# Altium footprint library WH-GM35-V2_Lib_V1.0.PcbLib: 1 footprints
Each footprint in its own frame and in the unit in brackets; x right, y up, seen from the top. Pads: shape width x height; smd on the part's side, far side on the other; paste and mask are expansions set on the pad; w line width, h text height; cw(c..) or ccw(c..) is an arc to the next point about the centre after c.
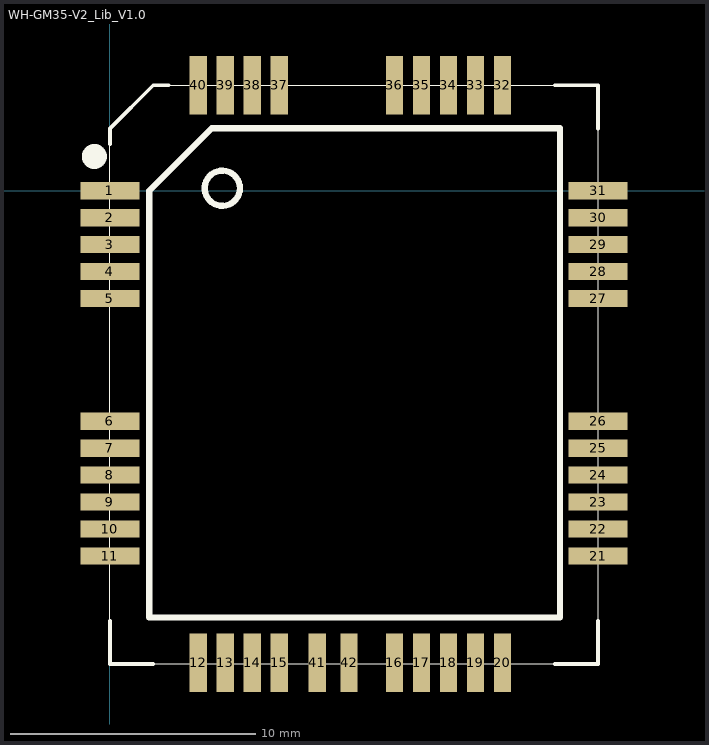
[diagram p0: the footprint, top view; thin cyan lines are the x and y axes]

## WH-GM35-V2_Lib_V1.0 [mm]
pads (42):
  rect 2.4x0.7 smd: 1(0,0) 2(0,-1.1) 3(0,-2.2) 4(0,-3.3) 5(0,-4.4) 6(0,-9.4) 7(0,-10.5) 8(0,-11.6) 9(0,-12.7) 10(0,-13.8) 11(0,-14.9) 21(19.9,-14.9) 22(19.9,-13.8) 23(19.9,-12.7) 24(19.9,-11.6) 25(19.9,-10.5) 26(19.9,-9.4) 27(19.9,-4.4) 28(19.9,-3.3) 29(19.9,-2.2) 30(19.9,-1.1) 31(19.9,0)
  rect 0.7x2.4 smd: 12(3.6,-19.25) 13(4.7,-19.25) 14(5.8,-19.25) 15(6.9,-19.25) 16(11.6,-19.25) 17(12.7,-19.25) 18(13.8,-19.25) 19(14.9,-19.25) 20(16,-19.25) 32(16,4.3) 33(14.9,4.3) 34(13.8,4.3) 35(12.7,4.3) 36(11.6,4.3) 37(6.9,4.3) 38(5.8,4.3) 39(4.7,4.3) 40(3.6,4.3) 41(8.45,-19.25) 42(9.75,-19.25)
Top Overlay:
  circle w0.254: c4.582,0.1 r0.718
  circle w0.762: c-0.635,1.397 r0.127
  lines w0.025: 0,2.54 0,-19.3 19.9,-19.3 19.9,4.3 1.76,4.3
  lines w0.152: 0,-17.54 0,-19.3 1.76,-19.3 ; 0,1.905 0,2.54 1.76,4.3 2.395,4.3 ; 18.14,-19.3 19.9,-19.3 19.9,-17.54 ; 18.14,4.3 19.9,4.3 19.9,2.54
  lines w0.254: 1.6,-17.4 18.35,-17.4 18.35,2.55 4.15,2.55 1.6,0 1.6,-17.4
